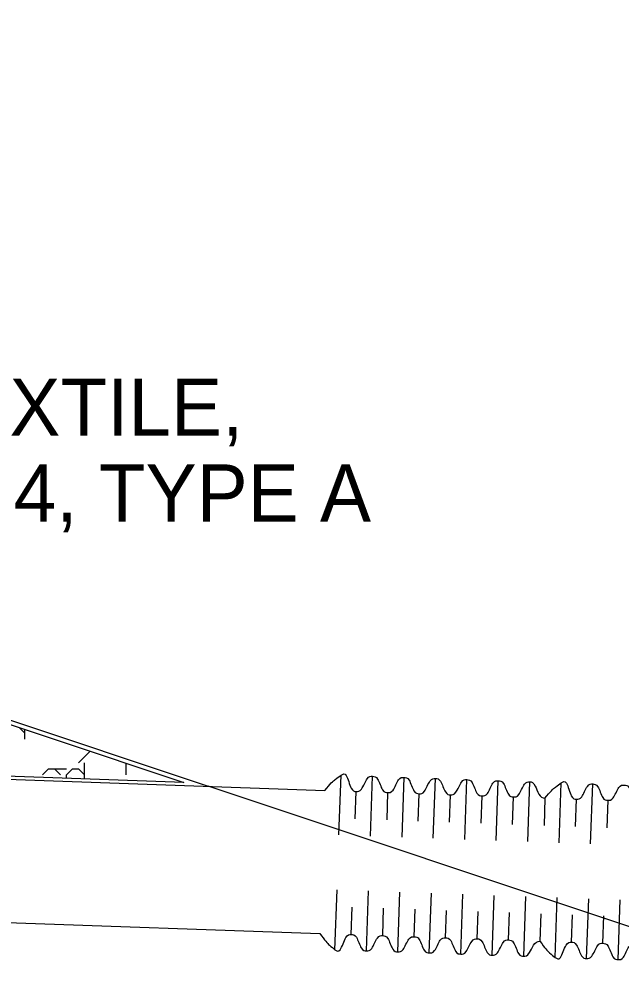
# Model space of a CAD drawing. Extents: x 636462 to 639890, y 299944 to 300538.
# Drawn here: x 638566.31 to 638597.86, y 300365.53 to 300415.03 of the extents above; entities that cross this region are included whole.
import ezdxf

# ---------------------------------------------------------------- set-up
doc = ezdxf.new("R2010")
doc.units = 0
doc.layers.add('Default', color=7, linetype='Continuous')

msp = doc.modelspace()

# ---------------------------------------------------------------- linework, layer by layer
at = {"layer": 'Default'}
for p, q in [((638455.666, 300415.029), (638576.237, 300374.838)), ((638470.52, 300378.53), (638582.339, 300374.625)), ((638566.62, 300377.627), (638566.322, 300377.926)), ((638566.62, 300377.314), (638566.62, 300377.826)), ((638569.431, 300376.065), (638570.047, 300376.681)), ((638567.557, 300375.441), (638567.87, 300375.753)), ((638567.87, 300375.753), (638568.807, 300375.753)), ((638568.494, 300375.441), (638568.182, 300375.753)), ((638568.807, 300375.441), (638569.119, 300375.753)), ((638569.119, 300375.753), (638569.431, 300375.753)), ((638569.743, 300375.441), (638569.431, 300375.753)), ((638569.743, 300375.227), (638569.743, 300376.065)), ((638571.929, 300375.441), (638571.929, 300376.053)), ((638568.807, 300375.26), (638568.807, 300375.441)), ((638583.083, 300372.289), (638583.192, 300375.42)), ((638584.731, 300372.231), (638584.84, 300375.363)), ((638586.486, 300375.305), (638586.377, 300372.174)), ((638588.024, 300372.116), (638588.134, 300375.248)), ((638589.672, 300372.059), (638589.782, 300375.19)), ((638591.32, 300372.001), (638591.43, 300375.133)), ((638601.369, 300366.461), (638576.237, 300374.838)), ((638592.968, 300371.944), (638593.078, 300375.075)), ((638594.616, 300371.886), (638594.726, 300375.018)), ((638596.264, 300371.829), (638596.373, 300374.96)), ((638583.937, 300373.132), (638583.987, 300374.568)), ((638585.633, 300374.51), (638585.583, 300373.075)), ((638587.231, 300373.017), (638587.281, 300374.453)), ((638588.879, 300372.959), (638588.929, 300374.395)), ((638590.527, 300372.902), (638590.577, 300374.338)), ((638592.175, 300372.844), (638592.225, 300374.28)), ((638593.873, 300374.223), (638593.823, 300372.787)), ((638595.47, 300372.727), (638595.521, 300374.165)), ((638597.169, 300374.107), (638597.118, 300372.67)), ((638470.258, 300371.04), (638582.078, 300367.135)), ((638582.873, 300366.282), (638582.982, 300369.413)), ((638584.521, 300366.224), (638584.63, 300369.356)), ((638586.167, 300366.167), (638586.276, 300369.298)), ((638587.815, 300366.109), (638587.924, 300369.241)), ((638589.463, 300366.052), (638589.572, 300369.183)), ((638591.111, 300365.994), (638591.22, 300369.126)), ((638592.758, 300365.937), (638592.868, 300369.068)), ((638594.406, 300365.879), (638594.516, 300369.011)), ((638596.054, 300365.822), (638596.164, 300368.953)), ((638597.702, 300365.764), (638597.812, 300368.896)), ((638583.726, 300367.077), (638583.776, 300368.515)), ((638585.372, 300367.02), (638585.422, 300368.457)), ((638587.02, 300366.962), (638587.07, 300368.4)), ((638588.667, 300366.905), (638588.718, 300368.342)), ((638590.315, 300366.847), (638590.366, 300368.285)), ((638591.963, 300366.79), (638592.013, 300368.227)), ((638593.661, 300368.168), (638593.611, 300366.732)), ((638595.259, 300366.674), (638595.309, 300368.11)), ((638596.907, 300366.617), (638596.957, 300368.053))]:
    msp.add_line(p, q, dxfattribs=at)
msp.add_lwpolyline([(638409.872, 300407.166), (638479.046, 300407.071), (638574.957, 300375.042), (638559.723, 300375.582), (638478.369, 300402.586), (638417.7, 300402.605)], close=True, dxfattribs=at)
for points in [[(638582.339, 300374.625), (638582.627, 300374.982), (638582.911, 300375.236), (638583.192, 300375.42), (638583.474, 300375.605), (638583.713, 300374.577), (638583.987, 300374.568), (638584.262, 300374.558), (638584.565, 300375.373), (638584.84, 300375.363), (638585.114, 300375.353), (638585.359, 300374.52), (638585.633, 300374.51), (638585.908, 300374.501), (638586.211, 300375.315), (638586.486, 300375.305), (638586.761, 300375.296), (638587.006, 300374.462), (638587.281, 300374.453), (638587.556, 300374.443), (638587.859, 300375.257), (638588.134, 300375.248), (638588.408, 300375.238), (638588.654, 300374.405), (638588.929, 300374.395), (638589.204, 300374.386), (638589.507, 300375.2), (638589.782, 300375.19), (638590.056, 300375.181), (638590.302, 300374.347), (638590.577, 300374.338), (638590.852, 300374.328), (638591.155, 300375.142), (638591.43, 300375.133), (638591.704, 300375.123), (638591.95, 300374.29), (638592.225, 300374.28), (638592.5, 300374.27), (638592.803, 300375.085), (638593.078, 300375.075), (638593.352, 300375.066), (638593.596, 300374.18), (638593.873, 300374.223)], [(638593.873, 300374.223), (638594.16, 300374.579), (638594.444, 300374.833), (638594.726, 300375.018), (638595.007, 300375.203), (638595.246, 300374.175), (638595.521, 300374.165), (638595.795, 300374.155), (638596.099, 300374.97), (638596.373, 300374.96), (638596.648, 300374.951), (638596.894, 300374.117), (638597.169, 300374.107), (638597.443, 300374.098), (638597.747, 300374.912), (638598.021, 300374.903), (638598.296, 300374.893), (638598.542, 300374.059), (638598.817, 300374.05), (638599.091, 300374.04), (638599.395, 300374.855), (638599.669, 300374.845), (638599.944, 300374.835), (638600.19, 300374.002), (638600.464, 300373.992), (638600.739, 300373.983), (638601.043, 300374.797), (638601.317, 300374.788), (638601.592, 300374.778), (638601.838, 300373.944), (638602.112, 300373.935), (638602.387, 300373.925), (638602.69, 300374.74), (638602.965, 300374.73), (638603.24, 300374.72), (638603.486, 300373.887), (638603.76, 300373.877), (638604.035, 300373.868), (638604.338, 300374.682), (638604.613, 300374.672), (638604.888, 300374.663), (638605.132, 300373.778), (638605.408, 300373.82)], [(638582.078, 300367.135), (638582.34, 300366.759), (638582.605, 300366.486), (638582.873, 300366.282), (638583.141, 300366.078), (638583.451, 300367.087), (638583.726, 300367.077), (638584, 300367.068), (638584.246, 300366.234), (638584.521, 300366.224), (638584.795, 300366.215), (638585.097, 300367.029), (638585.372, 300367.02), (638585.646, 300367.01), (638585.892, 300366.176), (638586.167, 300366.167), (638586.441, 300366.157), (638586.745, 300366.972), (638587.02, 300366.962), (638587.294, 300366.953), (638587.54, 300366.119), (638587.815, 300366.109), (638588.089, 300366.1), (638588.393, 300366.914), (638588.667, 300366.905), (638588.942, 300366.895), (638589.188, 300366.061), (638589.463, 300366.052), (638589.737, 300366.042), (638590.041, 300366.857), (638590.315, 300366.847), (638590.59, 300366.837), (638590.836, 300366.004), (638591.111, 300365.994), (638591.385, 300365.985), (638591.689, 300366.799), (638591.963, 300366.79), (638592.238, 300366.78), (638592.484, 300365.946), (638592.758, 300365.937), (638593.033, 300365.927), (638593.337, 300366.742), (638593.611, 300366.732)], [(638593.611, 300366.732), (638593.873, 300366.356), (638594.139, 300366.083), (638594.406, 300365.879), (638594.674, 300365.675), (638594.984, 300366.684), (638595.259, 300366.674), (638595.534, 300366.665), (638595.78, 300365.831), (638596.054, 300365.822), (638596.329, 300365.812), (638596.632, 300366.626), (638596.907, 300366.617), (638597.182, 300366.607), (638597.428, 300365.774), (638597.702, 300365.764), (638597.977, 300365.755), (638598.28, 300366.569), (638598.555, 300366.559), (638598.83, 300366.55), (638599.076, 300365.716), (638599.35, 300365.707), (638599.625, 300365.697), (638599.928, 300366.511), (638600.203, 300366.502), (638600.478, 300366.492), (638600.723, 300365.659), (638600.998, 300365.649), (638601.273, 300365.639), (638601.576, 300366.454), (638601.851, 300366.444), (638602.125, 300366.435), (638602.371, 300365.601), (638602.646, 300365.592), (638602.921, 300365.582), (638603.224, 300366.396), (638603.499, 300366.387), (638603.773, 300366.377), (638604.019, 300365.544), (638604.294, 300365.534), (638604.569, 300365.524), (638604.872, 300366.339), (638605.147, 300366.329)]]:
    msp.add_open_spline(points, degree=3, dxfattribs=at)

# ---------------------------------------------------------------- texts
for s, p in [('GEOTEXTILE,', (638551.784, 300393.196)), ('CLASS 4, TYPE A', (638551.784, 300388.699))]:
    msp.add_text(s, height=2.99804, dxfattribs=at).set_placement(p)

doc.saveas('drawing.dxf')
